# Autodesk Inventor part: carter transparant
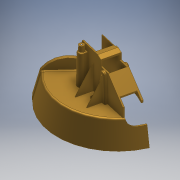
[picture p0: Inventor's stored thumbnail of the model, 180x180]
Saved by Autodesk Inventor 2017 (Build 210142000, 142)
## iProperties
Created: 2013-10
Part Number: carter transparant
Material: Laiton, jaune doux
Document SubType Name: Modeling
Designer: Bruno
Density: 8.47 g/cm^3
Appearance: Laiton - Satiné
Mass: 567.707 g
Surface Area: 714.266 cm^2
Volume: 67.0257 cm^3
Sending System: SolidWorks 2013
Last Author: christophe
Last Saved: 2014-02-15
Author: Bruno
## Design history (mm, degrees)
feature "Enlèv. mat.-Extru.33"
node "Solide1"
